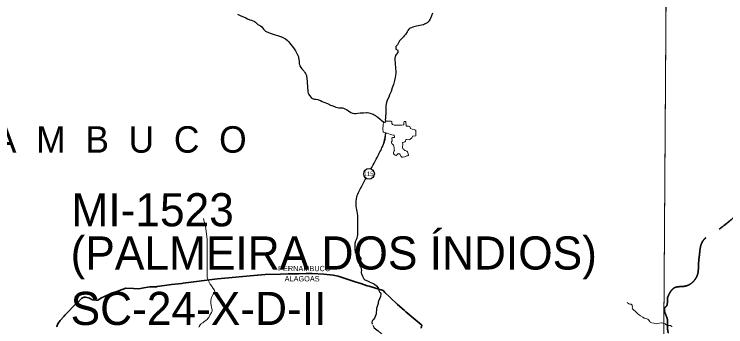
# Model space of a CAD drawing. Extents: x -1643653 to 4543381, y 1624270 to 13878484.
# Drawn here: x 608778 to 619526, y 8914272 to 8918990 of the extents above; entities that cross this region are included whole.
import ezdxf
from ezdxf.enums import TextEntityAlignment as Align

# ---------------------------------------------------------------- set-up
doc = ezdxf.new("R2010")
doc.units = 0
doc.header["$LTSCALE"] = 200
doc.linetypes.add('LONG_DASH_SHORT_DASH', pattern=[9.9, 6, -1.2, 1.5, -1.2])
doc.layers.add('6', color=7, linetype='Continuous', lineweight=13)
doc.layers.add('60', color=7, linetype='Continuous', lineweight=13)

msp = doc.modelspace()

# ---------------------------------------------------------------- linework, layer by layer
at = {"layer": '6'}
for points in [[(618663, 8924716.1), (618558.3, 8909803.7), (618456.5, 8896026.7)], [(614483.2, 8917364.6), (614467.6, 8917375.6), (614463.6, 8917376.8), (614453.8, 8917377.7), (614444.2, 8917377.6), (614431.3, 8917375.7), (614385.4, 8917375.3), (614384, 8917372.7), (614382.5, 8917355.8), (614381.6, 8917353.6), (614380.6, 8917353), (614371.5, 8917357.8), (614364.5, 8917363.7), (614359.8, 8917365.4), (614357.8, 8917364.7), (614356.5, 8917361.6), (614356.1, 8917349.2), (614353.3, 8917329.6)], [(614754.6, 8917297.1), (614733.7, 8917298.2), (614724.5, 8917300), (614706.9, 8917300.4), (614702, 8917302.9), (614698.8, 8917306.7), (614697.9, 8917309.7), (614696.4, 8917329.6), (614694, 8917343.6), (614693.5, 8917367.8), (614692.8, 8917370.2), (614690.8, 8917372), (614681.8, 8917371.7), (614672.2, 8917370.2), (614669.4, 8917368.8), (614666.2, 8917365.5), (614663.2, 8917356.2), (614663.8, 8917341.7), (614663.2, 8917328.7), (614662.2, 8917325.2), (614660, 8917322.9), (614651.8, 8917318.6), (614629, 8917315.1), (614600.7, 8917313.7), (614533.6, 8917313.3), (614519, 8917315.1), (614506.1, 8917319.2), (614494.5, 8917328), (614481.7, 8917339.9), (614481.1, 8917343.5), (614483.2, 8917364.6)], [(614353.3, 8917329.6), (614352.2, 8917322.5), (614345.4, 8917254.8), (614346.6, 8917239.4), (614349.3, 8917228.1), (614353.7, 8917214.1), (614355.6, 8917211.7), (614362.8, 8917207.7), (614378.2, 8917205), (614388.2, 8917198.8), (614393.1, 8917196.6), (614412.6, 8917194.1), (614462.2, 8917176.4), (614503.3, 8917166.5), (614515, 8917162.3), (614517.5, 8917160.8), (614518.9, 8917158.9), (614522.1, 8917148.6), (614522.7, 8917136.3), (614521.3, 8917132.7), (614518.9, 8917130.3), (614516.8, 8917129.5), (614495.6, 8917127.6), (614483, 8917118.2), (614480.4, 8917115.3), (614480.3, 8917112.9), (614487.5, 8917083.9), (614486.7, 8917078.9), (614477.9, 8917062.9), (614477.3, 8917052.7), (614478.1, 8917047.9), (614483, 8917038.8), (614487.4, 8917033.9), (614489.4, 8917030.1), (614498.1, 8917024.2), (614507.4, 8917015.4), (614511.4, 8917004.5), (614515.9, 8916965.9), (614518.6, 8916951.4), (614520.9, 8916933.1), (614519.2, 8916926.9), (614509.1, 8916901.4), (614507.7, 8916890.2), (614509.2, 8916886.2), (614519.8, 8916873.1), (614532.6, 8916862.9), (614541.2, 8916858.4), (614545.4, 8916858), (614550.8, 8916860.4), (614566.3, 8916872.1), (614577.3, 8916887.6), (614579.4, 8916887.7), (614596.1, 8916881.7), (614602.2, 8916877.5), (614623.1, 8916841.3), (614631.5, 8916834), (614635.1, 8916832.2), (614649.8, 8916834.1), (614675, 8916839.8), (614707.6, 8916850.7), (614717.6, 8916851.6), (614728.4, 8916856.1), (614731, 8916858.2), (614731.8, 8916860.8), (614732, 8916869.7), (614729, 8916885), (614724.2, 8916898.8), (614718.7, 8916911.5), (614709.1, 8916922.6), (614678.3, 8916934.4), (614666, 8916942.9), (614660.6, 8916947.7), (614651.9, 8916958.9), (614649.5, 8916963), (614644.2, 8916978.8), (614642.4, 8916992.8), (614642.8, 8916999.8), (614647.8, 8917020.1), (614649, 8917032.2), (614648.6, 8917035.4), (614644.7, 8917046.4), (614644.5, 8917049.5), (614646.4, 8917051.6), (614655.8, 8917055.8), (614670.9, 8917058.1), (614670.9, 8917058.1), (614679.8, 8917064), (614686.2, 8917073.9), (614695.3, 8917094), (614698.4, 8917097.6), (614703.1, 8917098.5), (614706.9, 8917100.2), (614741.6, 8917095.3), (614745.8, 8917095.9), (614752.8, 8917099), (614760.2, 8917105.8), (614781.6, 8917121.4), (614783.9, 8917125), (614792.6, 8917144.4), (614795.2, 8917147.3), (614803.3, 8917150.6)], [(614353.3, 8917329.6), (614352.2, 8917322.5), (614345.4, 8917254.8), (614346.6, 8917239.4), (614349.3, 8917228.1), (614353.7, 8917214.1), (614355.6, 8917211.7), (614362.8, 8917207.7), (614378.2, 8917205), (614388.2, 8917198.8), (614393.1, 8917196.6), (614412.6, 8917194.1), (614462.2, 8917176.4), (614503.3, 8917166.5), (614515, 8917162.3), (614517.5, 8917160.8), (614518.9, 8917158.9), (614522.1, 8917148.6), (614522.7, 8917136.3), (614521.3, 8917132.7), (614518.9, 8917130.3), (614516.8, 8917129.5), (614495.6, 8917127.6), (614483, 8917118.2), (614480.4, 8917115.3), (614480.3, 8917112.9), (614487.5, 8917083.9), (614486.7, 8917078.9), (614477.9, 8917062.9), (614477.3, 8917052.7), (614478.1, 8917047.9), (614483, 8917038.8), (614487.4, 8917033.9), (614489.4, 8917030.1), (614498.1, 8917024.2), (614507.4, 8917015.4), (614511.4, 8917004.5), (614515.9, 8916965.9), (614518.6, 8916951.4), (614520.9, 8916933.1), (614519.2, 8916926.9), (614509.1, 8916901.4), (614507.7, 8916890.2), (614509.2, 8916886.2), (614519.8, 8916873.1), (614532.6, 8916862.9), (614541.2, 8916858.4), (614545.4, 8916858), (614550.8, 8916860.4), (614566.3, 8916872.1), (614577.3, 8916887.6), (614579.4, 8916887.7), (614596.1, 8916881.7), (614602.2, 8916877.5), (614623.1, 8916841.3), (614631.5, 8916834), (614635.1, 8916832.2), (614649.8, 8916834.1), (614675, 8916839.8), (614707.6, 8916850.7), (614717.6, 8916851.6), (614728.4, 8916856.1), (614731, 8916858.2), (614731.8, 8916860.8), (614732, 8916869.7), (614729, 8916885), (614724.2, 8916898.8), (614718.7, 8916911.5), (614709.1, 8916922.6), (614678.3, 8916934.4), (614666, 8916942.9), (614660.6, 8916947.7), (614651.9, 8916958.9), (614649.5, 8916963), (614644.2, 8916978.8), (614642.4, 8916992.8), (614642.8, 8916999.8), (614647.8, 8917020.1), (614649, 8917032.2), (614648.6, 8917035.4), (614644.7, 8917046.4), (614644.5, 8917049.5), (614646.4, 8917051.6), (614655.8, 8917055.8), (614670.9, 8917058.1), (614670.9, 8917058.1), (614679.8, 8917064), (614686.2, 8917073.9), (614695.3, 8917094), (614698.4, 8917097.6), (614703.1, 8917098.5), (614706.9, 8917100.2), (614741.6, 8917095.3), (614745.8, 8917095.9), (614752.8, 8917099), (614760.2, 8917105.8), (614781.6, 8917121.4), (614783.9, 8917125), (614792.6, 8917144.4), (614795.2, 8917147.3), (614803.3, 8917150.6)], [(614803.3, 8917150.6), (614839.9, 8917152.8), (614843, 8917153.9), (614845.1, 8917157.9), (614846.9, 8917168.8), (614846.5, 8917221.4), (614842.3, 8917237.2), (614839.1, 8917240.5), (614821.9, 8917248.8), (614788.1, 8917253), (614766.1, 8917266), (614762.5, 8917269.1), (614757.1, 8917276.5), (614755.7, 8917295), (614754.6, 8917297.1), (614754.6, 8917297.1)], [(614803.3, 8917150.6), (614839.9, 8917152.8), (614843, 8917153.9), (614845.1, 8917157.9), (614846.9, 8917168.8), (614846.5, 8917221.4), (614842.3, 8917237.2), (614839.1, 8917240.5), (614821.9, 8917248.8), (614788.1, 8917253), (614766.1, 8917266), (614762.5, 8917269.1), (614757.1, 8917276.5), (614755.7, 8917295), (614754.6, 8917297.1), (614754.6, 8917297.1)], [(611636.1, 8915904.7), (611671, 8915753.7), (611694.2, 8915591.1), (611691.9, 8915020), (611701.8, 8914992.6)], [(611701.8, 8914992.6), (611709.5, 8914973.9), (611717.8, 8914957.2), (611728.7, 8914937.8), (611733.3, 8914927.2), (611738.5, 8914917.8), (611758.7, 8914890.3), (611784.6, 8914852.3), (611805.4, 8914826.5), (611808.3, 8914799.7), (611808.3, 8914799.7), (611808.3, 8914799.7), (611808.3, 8914799.7), (611785.5, 8914766.1), (611759.3, 8914712), (611752.6, 8914694.7), (611748.8, 8914667.4), (611748.6, 8914646.5), (611749.8, 8914628.6), (611755.2, 8914591.8), (611757.1, 8914572.4), (611762.5, 8914542.9), (611767.8, 8914528), (611767.7, 8914505.5), (611764.2, 8914496.9), (611758.8, 8914486.9), (611732.2, 8914447.5), (611716.2, 8914412.1), (611704.3, 8914394.9), (611693.1, 8914382.8), (611678.9, 8914371), (611658.2, 8914357.9), (611644, 8914347.7), (611629.4, 8914333.4), (611613.3, 8914326.6), (611603.6, 8914319.1), (611594.8, 8914310.6), (611588.4, 8914302.7), (611574.1, 8914274.6), (611566.6, 8914264.4)], [(618037.1, 8914636.8), (618063.1, 8914617.4), (618075.9, 8914614.9), (618091.6, 8914613.9), (618099.3, 8914611.9), (618104.2, 8914608.1), (618112.1, 8914596.2), (618114.9, 8914590), (618116.1, 8914575.1), (618115, 8914553), (618116, 8914545.1), (618117.5, 8914541.8), (618121.2, 8914536.8), (618130.5, 8914527.1), (618163, 8914504.1), (618174.3, 8914493), (618183.3, 8914480.9), (618200.4, 8914465.2), (618222.8, 8914449.4), (618238.7, 8914439.3), (618272.1, 8914415.7), (618291.4, 8914404.1), (618305.3, 8914399.8), (618336.2, 8914394.3), (618350.7, 8914387.1), (618360.7, 8914378.7), (618380.5, 8914349.5), (618386.6, 8914342.7), (618394.8, 8914336.7), (618410.6, 8914330.4), (618440.7, 8914327), (618454.9, 8914323.2), (618485.7, 8914318.9), (618499.1, 8914320), (618550, 8914333.9), (618557.9, 8914333.7), (618577.9, 8914326)]]:
    msp.add_lwpolyline(points, dxfattribs=at)
msp.add_lwpolyline([(618636, 8920869.6), (626625.7, 8920820.5), (626625.7, 8909822.1), (618558.7, 8909851.2)], close=True, dxfattribs=at)
at = {"layer": '6', "lineweight": 25}
for points in [[(612151.9, 8918992.2), (612169.6, 8918981.6), (612192.6, 8918970.1), (612274.7, 8918934.8), (612302.5, 8918921.1), (612336.9, 8918907.4), (612362.6, 8918900.8), (612405.6, 8918882.2), (612421.5, 8918871.9), (612438.8, 8918856.4), (612446.9, 8918846), (612459.3, 8918835.4), (612476.1, 8918824.3), (612499.9, 8918813.2), (612520.9, 8918801.1), (612545.9, 8918764.4), (612552.3, 8918756.7), (612574.4, 8918737.1), (612585.4, 8918729.8), (612621.2, 8918712.9), (612657.1, 8918698.9), (612675.5, 8918694.1), (612687.4, 8918691.8), (612785.1, 8918658.3), (612798.6, 8918656.1), (612805.9, 8918654), (612857.6, 8918631.4), (612868.1, 8918625.6), (612877.8, 8918618.5), (612906.6, 8918592), (612925, 8918571.6), (612936, 8918557.8)], [(615097.1, 8919008.6), (615080.7, 8918964.7), (615078, 8918952), (615073.3, 8918936.3), (615067.9, 8918928.8), (615056.1, 8918905.9)], [(615056.1, 8918905.9), (615045.1, 8918890.3), (615043.1, 8918886.4), (615040.6, 8918884.2), (615033.4, 8918874.7), (615025.2, 8918866.7), (615016.3, 8918860), (614996.2, 8918850.8), (614976, 8918839.6), (614959.7, 8918832.5), (614928.1, 8918826.1), (614907.5, 8918820.6), (614886.8, 8918817.4), (614854.4, 8918809.5), (614834.5, 8918806.1), (614813.7, 8918801.4), (614759.1, 8918777.8)], [(614759.1, 8918777.8), (614749.1, 8918773.5), (614739.6, 8918764.2), (614725.9, 8918746.1), (614712.8, 8918722.4), (614690.3, 8918685.3), (614670.7, 8918662.7), (614657.6, 8918649.8), (614630.2, 8918619.6), (614617.7, 8918607.8), (614599.4, 8918588.3), (614592.2, 8918578.2), (614566.7, 8918530.9), (614544.1, 8918501.6), (614541.6, 8918495.7), (614540.2, 8918484.7), (614541.4, 8918466.5), (614543.3, 8918464.1), (614550.3, 8918458.5), (614564, 8918453.3), (614567, 8918450.8), (614571.2, 8918444.2), (614573.7, 8918435.3), (614575.3, 8918425), (614571.8, 8918413.4), (614549.4, 8918381.8), (614539.5, 8918365.2), (614530.1, 8918343.9), (614527.7, 8918332.9), (614527.2, 8918311.5), (614528.1, 8918290.9), (614531, 8918261.4), (614534.3, 8918240.8), (614534.5, 8918229.7), (614537.8, 8918190), (614539.5, 8918178.1), (614542.1, 8918126.6), (614541, 8918106.7), (614541.7, 8918093.4), (614539.3, 8918065.4), (614533.7, 8918034.5), (614528.6, 8918013.8), (614524.9, 8917992.4), (614519, 8917971.8), (614514.6, 8917951.2), (614508.3, 8917932), (614488.8, 8917879.7), (614470.7, 8917825.6), (614446.7, 8917773.9), (614446.7, 8917773.9), (614434.9, 8917740.8), (614412.3, 8917691.4), (614401.7, 8917659.5), (614394, 8917611.3), (614393.1, 8917598.4)], [(614759.1, 8918777.8), (614749.1, 8918773.5), (614739.6, 8918764.2), (614725.9, 8918746.1), (614712.8, 8918722.4), (614690.3, 8918685.3), (614670.7, 8918662.7), (614657.6, 8918649.8), (614630.2, 8918619.6), (614617.7, 8918607.8), (614599.4, 8918588.3), (614592.2, 8918578.2), (614566.7, 8918530.9), (614544.1, 8918501.6), (614541.6, 8918495.7), (614540.2, 8918484.7), (614541.4, 8918466.5), (614543.3, 8918464.1), (614550.3, 8918458.5), (614564, 8918453.3), (614567, 8918450.8), (614571.2, 8918444.2), (614573.7, 8918435.3), (614575.3, 8918425), (614571.8, 8918413.4), (614549.4, 8918381.8), (614539.5, 8918365.2), (614530.1, 8918343.9), (614527.7, 8918332.9), (614527.2, 8918311.5), (614528.1, 8918290.9), (614531, 8918261.4), (614534.3, 8918240.8), (614534.5, 8918229.7), (614537.8, 8918190), (614539.5, 8918178.1), (614542.1, 8918126.6), (614541, 8918106.7), (614541.7, 8918093.4), (614539.3, 8918065.4), (614533.7, 8918034.5), (614528.6, 8918013.8), (614524.9, 8917992.4), (614519, 8917971.8), (614514.6, 8917951.2), (614508.3, 8917932), (614488.8, 8917879.7), (614470.7, 8917825.6), (614446.7, 8917773.9), (614446.7, 8917773.9), (614434.9, 8917740.8), (614412.3, 8917691.4), (614401.7, 8917659.5), (614394, 8917611.3), (614393.1, 8917598.4)], [(612936, 8918557.8), (612997.1, 8918481.3), (613005, 8918467.7), (613025.2, 8918438.3), (613047.6, 8918398.7), (613052.8, 8918391), (613064.5, 8918366.6), (613070.3, 8918348.4), (613074, 8918332.2), (613082.4, 8918279.6), (613082, 8918256.2), (613082.6, 8918242.6), (613082.6, 8918242.6), (613085.9, 8918229.9), (613092.8, 8918212.1), (613108.1, 8918184.7), (613124.2, 8918164.5), (613133.9, 8918154.5), (613150.9, 8918135)], [(613150.9, 8918135), (613159.7, 8918124.9), (613162.5, 8918119.3), (613168.8, 8918110.8), (613178.8, 8918093.6), (613191.7, 8918064.1), (613195.4, 8918050.9), (613199.4, 8918022.9), (613201.6, 8917972), (613205.7, 8917947.5), (613206.9, 8917904.5), (613206.3, 8917894.3), (613211.1, 8917820.5), (613217.9, 8917799.9), (613227.3, 8917781), (613236.9, 8917763.9), (613262.2, 8917731.7), (613265.1, 8917729.8)], [(613265.1, 8917729.8), (613282.1, 8917718.9), (613293.1, 8917714.2), (613301.3, 8917711.7), (613313.8, 8917709.3), (613335.9, 8917707.7), (613362.5, 8917703.3), (613375, 8917699.4), (613406.2, 8917686.8), (613430.6, 8917674), (613454.4, 8917663), (613508.8, 8917641.6), (613554.7, 8917619.3), (613574.2, 8917611.6)], [(613574.2, 8917611.6), (613613.8, 8917596), (613636.9, 8917588), (613660.8, 8917581.6), (613679.3, 8917578), (613727.2, 8917578), (613739.2, 8917575.8), (613750.4, 8917572.4), (613774.2, 8917562.3), (613796.5, 8917551.9), (613828.6, 8917532.1), (613862.7, 8917507.3), (613887.1, 8917497), (613898.3, 8917495.2), (613919.8, 8917493.1), (613942.2, 8917493.4), (613967.8, 8917495.2), (614003.2, 8917499.8), (614037.7, 8917502.2), (614054.5, 8917501.7), (614098.7, 8917504.8), (614109.1, 8917504.6), (614135.4, 8917502.1), (614168.4, 8917492.9), (614197.5, 8917483.7), (614202.5, 8917481.3), (614216.3, 8917470), (614233.1, 8917460.2), (614240.3, 8917454.3), (614268.6, 8917436.6), (614304.5, 8917408.4), (614322.8, 8917391.2), (614356.9, 8917364.2)], [(614393.1, 8917598.4), (614392.3, 8917587.3), (614391.7, 8917555.6), (614390.4, 8917543.2), (614389.2, 8917509), (614389.5, 8917479.2), (614388.2, 8917460.3), (614385, 8917431.9), (614384.8, 8917413.7), (614383.7, 8917403.3), (614384.4, 8917375.7)], [(614393.1, 8917598.4), (614392.3, 8917587.3), (614391.7, 8917555.6), (614390.4, 8917543.2), (614389.2, 8917509), (614389.5, 8917479.2), (614388.2, 8917460.3), (614385, 8917431.9), (614384.8, 8917413.7), (614383.7, 8917403.3), (614384.4, 8917375.7)], [(614388.5, 8917198.5), (614377.2, 8917097.2), (614367.9, 8917071.3)], [(614365.7, 8917065), (614357.7, 8917036.4), (614353.7, 8917024.7), (614333.6, 8916975)], [(614150.8, 8914946.8), (614203.4, 8914923.6), (614219.2, 8914914.1), (614248.1, 8914891.9), (614274.4, 8914859), (614285.4, 8914820.3), (614297.9, 8914802), (614310.3, 8914787.6), (614314.4, 8914779.7), (614315.7, 8914772), (614315.9, 8914758.2), (614313.3, 8914740.9), (614309.4, 8914728.2), (614280.1, 8914656.7), (614276, 8914641.2), (614276.3, 8914628.6), (614275.7, 8914624.6), (614251.7, 8914550), (614243.4, 8914465), (614240.3, 8914452.2), (614231.3, 8914428.1), (614220.5, 8914404.5), (614198, 8914377.3), (614186.3, 8914359.4), (614184.7, 8914355.3), (614182, 8914339.1), (614187.1, 8914310.2)], [(614194.7, 8914296.6), (614216.1, 8914258.1), (614233.7, 8914242.9), (614276.3, 8914209.9), (614325.7, 8914164.7), (614338.8, 8914150.3), (614373.7, 8914115.3), (614379.8, 8914105.7)]]:
    msp.add_lwpolyline(points, dxfattribs=at)
at = {"layer": '6', "linetype": 'LONG_DASH_SHORT_DASH', "lineweight": 35}
for points in [[(612801.4, 8915066.3), (612801.4, 8915066.3), (612917.6, 8915073.7), (613074.1, 8915071.3), (613187.3, 8915075.4), (613275.3, 8915075.1), (613277.6, 8915078.3), (613454.2, 8915067.7), (613598.2, 8915052.7), (613669.1, 8915033.8), (613716.2, 8915018.8), (613926, 8914950.1), (614011.9, 8914925.2), (614110.4, 8914892.2), (614138, 8914884.1), (614349.8, 8914819.3), (614378.6, 8914788.4), (614454.1, 8914720.6), (614569.5, 8914609.1), (614667.9, 8914523.4), (614691.4, 8914498.4), (614934.5, 8914297.2), (614926, 8914253.5)], [(609414.5, 8914271.5), (609423.4, 8914278), (609438.5, 8914317.1), (609470.2, 8914368), (609534.8, 8914432.1), (609542.7, 8914447.8), (609726.2, 8914632.2), (609735.6, 8914633.7), (609801.8, 8914705.2), (609834.3, 8914720.4), (609853.1, 8914720.4), (609915.1, 8914705.6), (609951.4, 8914683.3), (609956.6, 8914684.2), (609962.2, 8914680.3), (610012.3, 8914673.4), (610039, 8914675), (610068.6, 8914686.7), (610088.4, 8914702.4), (610215.4, 8914764.3), (610462.8, 8914853.2), (610579.4, 8914851.9), (610659.1, 8914847.2), (610736.4, 8914857.9), (610829, 8914875.5), (610927.4, 8914877.4), (610939, 8914881.5), (611120.3, 8914903.8), (611152.1, 8914910.7), (611312, 8914924.8), (611328.8, 8914929.5), (611846.5, 8914996.4), (612450.8, 8915051.7), (612456.6, 8915048.8), (612566.7, 8915060.4), (612801.4, 8915066.3)]]:
    msp.add_lwpolyline(points, dxfattribs=at)
at = {"layer": '6', "lineweight": 25}
msp.add_circle((614137.6, 8916580.5), 80.3, dxfattribs=at)
at = {"layer": '6', "lineweight": 40}
msp.add_spline([(605233.4, 8918291.8), (605425.1, 8918291.8), (605556.8, 8918274.6), (605694.1, 8918217.3), (605780, 8918168.6), (605911.6, 8918165.8), (606008.9, 8918211.6), (606114.8, 8918211.6), (606197.8, 8918134.3), (606353.7, 8918138.6), (606551.2, 8918198.7), (606637.1, 8918198.7), (606903.2, 8918104.2), (607195.1, 8918130), (607418.3, 8918172.9), (607555.7, 8918130), (607658.7, 8918138.6), (607753.1, 8918172.9), (607813.2, 8918172.9), (607967.8, 8918353.3), (608139.5, 8918542.3), (608208.1, 8918748.4), (608345.5, 8918868.7), (608508.6, 8918946), (608680.3, 8919186.5), (608766.2, 8919298.2), (608826.3, 8919384.1), (608920.7, 8919409.8), (609058.1, 8919427), (609126.8, 8919444.2), (609186.8, 8919512.9), (609272.7, 8919538.7), (609418.7, 8919530.1), (609633.3, 8919581.6), (609805, 8919650.3), (609950.9, 8919727.6), (610174.2, 8919847.9), (610285.8, 8919890.8), (610500.4, 8919959.5), (610612, 8920002.5), (610715, 8920002.5), (610989.7, 8919925.2)], degree=3, dxfattribs=at)
at = {"layer": '6', "lineweight": 25}
for points in [[(614167.1, 8916655.2), (614259.3, 8916826), (614342.6, 8917000.8), (614380.2, 8917124), (614389.7, 8917195.3)], [(614150.8, 8914946.8), (614106, 8914966.5), (614061.7, 8914993.4), (614044.2, 8915031), (614025.4, 8915082.1), (614026.7, 8915123.8), (614018.7, 8915166.8), (613997.1, 8915212.5), (614001.2, 8915255.5), (614018.7, 8915291.8), (614010.6, 8915320.1), (613970.2, 8915351), (613939.3, 8915383.2), (613929.9, 8915445.1), (613928.6, 8915515), (613931.3, 8915548.6), (613950.1, 8915591), (613968.9, 8915681.1), (613966.2, 8915794.1), (613967.6, 8915882.8), (613966.2, 8915952.8), (613947.4, 8916067.1), (613944.7, 8916151.8), (613954.1, 8916229.8), (613986.4, 8916318.6), (614006.6, 8916357.6), (614090, 8916512.3)]]:
    msp.add_spline(points, degree=3, dxfattribs=at)
at = {"layer": '6', "linetype": 'LONG_DASH_SHORT_DASH', "lineweight": 35}
for points in [[(618645.2, 8914712.1), (618757.5, 8914863.9), (618920, 8914886.7), (619101.3, 8915065.7), (619114.8, 8915216.7), (619131.1, 8915375.5), (619151.7, 8915505.9), (619183.6, 8915572), (619343.3, 8915692.3), (619623.9, 8915902.9), (619755.5, 8916013.4), (619958, 8916125.3), (620120.4, 8916140.4), (620332.3, 8916000.7), (620548.1, 8915914.9), (620684.2, 8915892), (620903.2, 8915836.8), (621033.8, 8915793.5), (621199.4, 8915729.1), (621321.7, 8915650), (621492.8, 8915605.9), (621656.5, 8915572.3), (621839, 8915694.8), (621982.5, 8915771.8), (622137.8, 8915920.4), (622201, 8916029.6), (622275.9, 8916097.5), (622361, 8916147.5)], [(618659, 8914177), (618649, 8914224.2), (618647.3, 8914329.3), (618641.9, 8914396), (618611.5, 8914473.8), (618614.6, 8914571), (618625, 8914578.4), (618644.7, 8914641.8), (618645.2, 8914712.1)]]:
    msp.add_spline(points, degree=3, dxfattribs=at)
at = {"layer": '6'}
msp.add_spline([(618577.9, 8914326), (618609.6, 8914316.1), (618618.6, 8914307.9), (618637.8, 8914294.4), (618644.9, 8914292.3), (618670.3, 8914293.1), (618688.6, 8914291.9), (618697.8, 8914288.7), (618703.8, 8914283.6), (618707.8, 8914279.4), (618712.8, 8914272.3)], degree=3, dxfattribs=at)
at = {"layer": '60', "lineweight": 25}
msp.add_spline([(814781, 9009175.5), (814787.2, 9009173.4), (814796.9, 9009173.4), (814799.4, 9009172.4), (814805.1, 9009174.5), (814805.6, 9009176.5), (814811.7, 9009179.5), (814811.7, 9009179.5), (814801.5, 9009181), (814790.7, 9009181.5), (814784.1, 9009183.1), (814777.4, 9009185.1), (814778.4, 9009175.5)], degree=3, dxfattribs=at)

# ---------------------------------------------------------------- texts
at = {"layer": '6'}
for s, height, p in [('P  E  R  N  A  M  B  U  C  O', 400, (605780.3, 8916899.9)), ('MI-1523', 500, (609642.6, 8915788.7)), ('(PALMEIRA DOS ÍNDIOS)', 500, (609630, 8915136.3)), ('SC-24-X-D-II', 500, (609630, 8914299.2))]:
    msp.add_text(s, height=height, dxfattribs=at).set_placement(p)
at = {"layer": '6', "width": 0.75}
msp.add_text('115', height=70, dxfattribs=at).set_placement((614131.3, 8916545.8), align=Align.CENTER)
at = {"layer": '6'}
for s, p in [('PERNAMBUCO', (613160.6, 8915111.6)), ('ALAGOAS', (613127.1, 8914956.9))]:
    msp.add_text(s, height=80, dxfattribs=at).set_placement(p, align=Align.CENTER)

doc.saveas('drawing.dxf')
